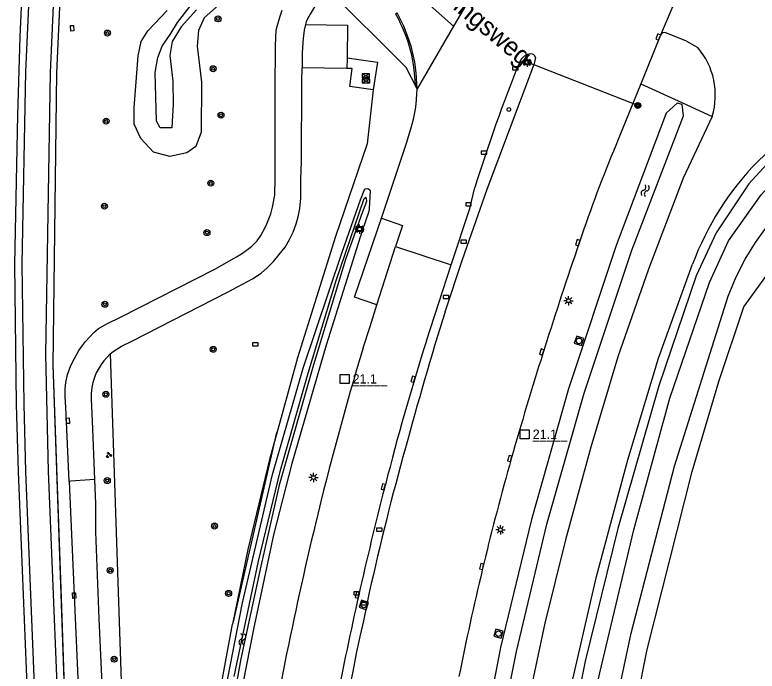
# Model space of a CAD drawing. Extents: x 124000 to 129000, y 395500 to 397503.
# Drawn here: x 124748.5 to 124848.4, y 396797.1 to 396885.3 of the extents above; entities that cross this region are included whole.
import ezdxf

# ---------------------------------------------------------------- set-up
doc = ezdxf.new("R2010")
doc.units = 0
for name, color, linetype in [('gg-afsc-draadraster', 7, 'Continuous'), ('gg-afsc-hekwerk', 7, 'Continuous'), ('gg-afsc-lijn draadraster', 7, 'Continuous'), ('gg-anno-openbare ruimte label', 7, 'Continuous'), ('gg-knt-bovenkant onderkant talud', 7, 'Continuous'), ('gg-knt-verharding', 7, 'Continuous'), ('gg-knt-verharding nz', 7, 'Continuous'), ('gg-kntw-bovenkant insteek waterloop', 7, 'Continuous'), ('gg-kntw-waterlijn', 7, 'Continuous'), ('gt-anno-nummer hm paal', 7, 'Continuous'), ('gt-grn-groengrens', 7, 'Continuous'), ('gt-grn-weggrens revisie', 7, 'Continuous'), ('gt-knt-lijn portaal', 7, 'Continuous'), ('gt-symb-boom', 7, 'Continuous'), ('gt-symb-bord', 7, 'Continuous'), ('gt-symb-groenvak', 7, 'Continuous'), ('gt-symb-hm paal', 7, 'Continuous'), ('gt-symb-kast', 7, 'Continuous'), ('gt-symb-kolk', 7, 'Continuous'), ('gt-symb-kolk center center', 7, 'Continuous'), ('gt-symb-lichtmast', 7, 'Continuous'), ('gt-symb-portaalmast', 7, 'Continuous'), ('gt-symb-rioolschacht', 7, 'Continuous'), ('gt-symb-verkeersregelinstallatiepaal', 7, 'Continuous'), ('gt-symb-watersymbool', 7, 'Continuous'), ('gx-grn-maaiveld', 7, 'Continuous')]:
    doc.layers.add(name, color=color, linetype=linetype)

# ---------------------------------------------------------------- blocks, each defined once
blk = doc.blocks.new('gt0-KOLK')
at = {"layer": 'gt-symb-kolk'}
blk.add_lwpolyline([(0, 0), (0.375, 0), (0.375, 0.4), (-0.375, 0.4), (-0.375, 0), (0, 0)], dxfattribs=at)
blk = doc.blocks.new('gt0-PORTM')
at = {"layer": 'gt-symb-portaalmast'}
for radius in [0.4, 0.33, 0.27, 0.21, 0.15]:
    blk.add_circle((0, 0), radius, dxfattribs=at)
blk = doc.blocks.new('gt0-WA')
at = {"layer": 'gt-symb-watersymbool'}
for centre, start, end in [((-0.323, 0.022), 28.07249, 151.92751), ((0.427, 0.422), 208.07248, 331.92751), ((-0.323, -0.428), 28.07249, 151.92751), ((0.427, -0.028), 208.07248, 331.92751)]:
    blk.add_arc(centre, 0.425, start, end, dxfattribs=at)
blk = doc.blocks.new('gt0-RS')
at = {"layer": 'gt-symb-rioolschacht'}
blk.add_lwpolyline([(-0.5, -0.5), (0.5, -0.5), (0.5, 0.5), (-0.5, 0.5)], close=True, dxfattribs=at)
blk.add_circle((0, 0), 0.375, dxfattribs=at)
blk = doc.blocks.new('gt0-LMAST')
at = {"layer": 'gt-symb-lichtmast'}
for p, q in [((-0.182, 0.173), (-0.447, 0.438)), ((-0.005, 0.246), (-0.005, 0.621)), ((0.172, 0.173), (0.437, 0.438)), ((-0.255, -0.004), (-0.63, -0.004)), ((-0.182, -0.181), (-0.447, -0.446)), ((-0.005, -0.254), (-0.005, -0.629)), ((0.437, -0.446), (0.172, -0.181)), ((0.245, -0.004), (0.62, -0.004))]:
    blk.add_line(p, q, dxfattribs=at)
blk.add_circle((-0.005, -0.004), 0.25, dxfattribs=at)
blk = doc.blocks.new('gt0-HMpaal')
at = {"layer": 'gt-symb-hm paal'}
blk.add_lwpolyline([(-0.6, 0.6), (0.6, 0.6), (0.6, -0.6), (-0.6, -0.6)], close=True, dxfattribs=at)
blk = doc.blocks.new('gt0-KAST')
at = {"layer": 'gt-symb-kast'}
for p, q in [((-0.501, -0.249), (0.501, 0.249)), ((-0.501, 0.249), (0.501, -0.249))]:
    blk.add_line(p, q, dxfattribs=at)
blk.add_lwpolyline([(0.501, 0.249), (-0.501, 0.249), (-0.501, -0.249), (0.501, -0.249)], close=True, dxfattribs=at)
blk = doc.blocks.new('gt0-BORD')
at = {"layer": 'gt-symb-bord'}
blk.add_lwpolyline([(-0.5, 0.295), (-0.5, -0.295), (0.5, -0.295), (0.5, 0.295), (-0.5, 0.295)], dxfattribs=at)
blk.add_lwpolyline([(-0.417, -0.212), (0.417, -0.212), (0.417, 0.212), (-0.417, 0.212)], close=True, dxfattribs=at)
blk = doc.blocks.new('gt0-BOOM')
at = {"layer": 'gt-symb-boom'}
for radius in [0.4, 0.2]:
    blk.add_circle((0, 0), radius, dxfattribs=at)
blk = doc.blocks.new('gt0-VIPAAL')
at = {"layer": 'gt-symb-verkeersregelinstallatiepaal'}
blk.add_circle((0, 0), 0.25, dxfattribs=at)
blk = doc.blocks.new('gt0-GRVAK')
at = {"layer": 'gt-symb-groenvak'}
for p, q in [((-0.11, 0.189), (-0.228, 0.24)), ((-0.182, 0.153), (0.088, 0.153)), ((-0.091, 0.211), (-0.156, 0.322)), ((-0.047, 0.214), (-0.047, 0.393)), ((-0.004, 0.211), (0.061, 0.322)), ((0.015, 0.189), (0.133, 0.24)), ((0.262, -0.052), (0.197, 0.059)), ((0.305, -0.049), (0.305, 0.13)), ((0.349, -0.052), (0.414, 0.059)), ((-0.245, -0.228), (-0.363, -0.177)), ((-0.318, -0.264), (-0.047, -0.264)), ((-0.226, -0.206), (-0.291, -0.095)), ((-0.183, -0.203), (-0.183, -0.024)), ((-0.139, -0.206), (-0.074, -0.095)), ((-0.12, -0.228), (-0.002, -0.177)), ((0.243, -0.074), (0.125, -0.023)), ((0.17, -0.11), (0.441, -0.11)), ((0.368, -0.074), (0.486, -0.023))]:
    blk.add_line(p, q, dxfattribs=at)
blk = doc.blocks.new('gt0-KOLKCC')
at = {"layer": 'gt-symb-kolk center center'}
blk.add_lwpolyline([(-0.375, 0.2), (0.375, 0.2), (0.375, -0.2), (-0.375, -0.2)], close=True, dxfattribs=at)

msp = doc.modelspace()

# ---------------------------------------------------------------- linework, layer by layer
at = {"layer": 'gg-afsc-draadraster'}
msp.add_lwpolyline([(124820.013, 396699.179), (124820.083, 396715.173), (124820.232, 396720.364), (124822.501, 396749.715), (124824.3, 396763.179), (124826.222, 396776.512), (124828.088, 396786.558), (124831.396, 396802.197), (124837.239, 396824.642), (124844.473, 396847.524), (124845.543, 396850.093), (124846.747, 396852.464), (124848.154, 396854.73), (124849.824, 396857.075), (124858.419, 396867.513)], dxfattribs=at)
at = {"layer": 'gg-afsc-hekwerk'}
msp.add_lwpolyline([(124759.38, 396710.74), (124755.634, 396783.08), (124753.682, 396838.231), (124754.182, 396877.515), (124755.955, 396916.668)], dxfattribs=at)
at = {"layer": 'gg-afsc-lijn draadraster'}
msp.add_line((124783.72, 396829.162), (124777.854, 396803.558), dxfattribs=at)
at = {"layer": 'gg-knt-bovenkant onderkant talud'}
msp.add_lwpolyline([(124822.564, 396699.278), (124822.903, 396713.454), (124824.661, 396738.834), (124825.256, 396746.56), (124827.056, 396763.66), (124828.802, 396774.037), (124830.867, 396786.503), (124833.575, 396800.029), (124839.594, 396823.963), (124843.199, 396836.04), (124846.57, 396846.056), (124850.8, 396851.948)], dxfattribs=at)
at = {"layer": 'gg-knt-verharding'}
for p, q in [((124835.38, 396882.586), (124832.712, 396876.032)), ((124838.863, 396881.775), (124836.078, 396882.903)), ((124838.863, 396881.775), (124840.359, 396880.945)), ((124832.712, 396876.032), (124829.68, 396868.564)), ((124848.355, 396865.523), (124851.006, 396868.084)), ((124824.787, 396855.717), (124824.412, 396854.624)), ((124797.226, 396846.331), (124799.744, 396854.174)), ((124803.877, 396841.511), (124807.226, 396851.707)), ((124815.533, 396826.526), (124815.282, 396825.625)), ((124798.357, 396822.149), (124798.267, 396821.835)), ((124808.457, 396797.379), (124808.246, 396796.387))]:
    msp.add_line(p, q, dxfattribs=at)
for points in [[(124818.529, 396879.592), (124818.477, 396879.183), (124818.304, 396878.592)], [(124806.392, 396845.399), (124808.754, 396852.437), (124812.029, 396861.904), (124818.051, 396877.832), (124818.304, 396878.592)], [(124842.318, 396871.666), (124838.42, 396863.381), (124833.725, 396851.122), (124829.62, 396839.34), (124825.983, 396827.223), (124822.6, 396814.773), (124819.808, 396803.556), (124816.441, 396787.758), (124813.837, 396771.712), (124811.667, 396754.763), (124810.203, 396737.809), (124809.074, 396719.01), (124808.896, 396703.076)], [(124797.859, 396857.999), (124801.219, 396868.062), (124801.795, 396869.985)], [(124807.226, 396851.707), (124809.71, 396859.304), (124810.382, 396862.089)], [(124797.226, 396846.331), (124794.201, 396847.356), (124797.859, 396857.999)], [(124797.859, 396857.999), (124800.673, 396857.026), (124799.744, 396854.174)], [(124814.177, 396707.412), (124814.434, 396721.809), (124815.265, 396735.042), (124816.512, 396750.349), (124818.326, 396765.688), (124820.487, 396780.485), (124823.023, 396793.705), (124826.755, 396809.814), (124830.977, 396825.495), (124835.088, 396839.152), (124839.682, 396851.814)], [(124795.369, 396840.546), (124796.309, 396843.432), (124797.226, 396846.331)], [(124796.194, 396807.661), (124795.405, 396803.892), (124794.953, 396801.953)]]:
    msp.add_lwpolyline(points, dxfattribs=at)
for centre, radius, start, end in [((124835.908, 396882.351), 0.578, 72.86521, 155.98559), ((124832.804, 396874.504), 9.928, 343.39083, 40.45183), ((124818.079, 396878.25), 1.824, 94.45874, 155.36281), ((124817.979, 396879.514), 0.556, 8.11559, 94.28208), ((125027.103, 396794.281), 227.081, 158.09166, 162.62601), ((124782.703, 396875.685), 19.925, 343.37635, 359.04471), ((125007.742, 396793.391), 193.28, 157.11177, 161.18785), ((124876.038, 396838.412), 38.747, 135.5973, 159.76371), ((125383.551, 396662.484), 591.231, 161.035419, 163.89139), ((125250.716, 396706.039), 465.666, 162.58619, 164.93069), ((125139.548, 396735.345), 352.06, 162.44891, 165.72597), ((125212.392, 396714.688), 435.601, 163.20616, 166.42726), ((125161.507, 396726.519), 374.216, 164.40752, 167.47701), ((125180.221, 396722.498), 379.23, 164.22044, 168.61186), ((125272.386, 396700.162), 489.482, 165.60678, 169.094), ((125267.899, 396701.714), 492.603, 166.47549, 170.91701), ((125510.359, 396655.849), 730.172, 168.457461, 170.029078)]:
    msp.add_arc(centre, radius, start, end, dxfattribs=at)
at = {"layer": 'gg-knt-verharding nz'}
msp.add_line((124839.921, 396893.347), (124835.38, 396882.586), dxfattribs=at)
at = {"layer": 'gg-kntw-bovenkant insteek waterloop'}
for points in [[(124806.413, 396692.247), (124806.146, 396711.167), (124806.637, 396728.332), (124807.854, 396746.225), (124810.08, 396765.886), (124812.639, 396783.003), (124816.014, 396799.727), (124820.095, 396816.858), (124825.097, 396834.491), (124831.511, 396853.689), (124838.433, 396871.724), (124838.256, 396873.281), (124837.594, 396873.455), (124836.139, 396872.088), (124829.383, 396854.324), (124822.973, 396835.044), (124817.992, 396817.504), (124813.85, 396800.299), (124810.555, 396783.323), (124808.002, 396765.983), (124805.831, 396746.365), (124804.631, 396728.673), (124804.085, 396711.233), (124804.281, 396692.296)], [(124852.568, 396868.625), (124851.592, 396867.354), (124847.232, 396862.618), (124842.846, 396856.025), (124840.145, 396850.258), (124835.154, 396835.474), (124829.61, 396816.277), (124825.222, 396798.437), (124821.651, 396780.387), (124819.119, 396763.426), (124817.031, 396745.202), (124815.931, 396727.225), (124815.605, 396713.346)], [(124815.605, 396713.346), (124817.753, 396713.346), (124818.009, 396726.766), (124819.222, 396745.231), (124821.034, 396762.339), (124823.493, 396780.248), (124827.178, 396796.897), (124831.761, 396816.101), (124836.629, 396833.777), (124841.935, 396849.343), (124844.503, 396854.958), (124848.914, 396861.116), (124853.86, 396866.625), (124854.424, 396867.427)]]:
    msp.add_lwpolyline(points, dxfattribs=at)
at = {"layer": 'gg-kntw-waterlijn'}
for points in [[(124781.288, 396811.879), (124784.265, 396824.122), (124787.995, 396837.155), (124791.755, 396849.627), (124795.527, 396860.625), (124795.685, 396860.789), (124795.738, 396860.795), (124795.793, 396860.653), (124795.831, 396860.28), (124795.7, 396859.85), (124795.291, 396858.84), (124793.013, 396852.423), (124788.709, 396838.296), (124784.075, 396822.118), (124781.622, 396811.205), (124778.933, 396798.776), (124777.491, 396790.749)], [(124778.016, 396796.375), (124781.288, 396811.879)]]:
    msp.add_lwpolyline(points, dxfattribs=at)
at = {"layer": 'gt-grn-groengrens'}
for p, q in [((124832.712, 396876.032), (124837.729, 396873.752)), ((124837.729, 396873.752), (124842.318, 396871.666))]:
    msp.add_line(p, q, dxfattribs=at)
msp.add_lwpolyline([(124766.657, 396718.624), (124768.688, 396721.592), (124769.253, 396729.69), (124768.876, 396733.645), (124769.065, 396740.99), (124769.253, 396745.698), (124772.831, 396776.397), (124777.816, 396803.404)], dxfattribs=at)
at = {"layer": 'gt-grn-weggrens revisie'}
msp.add_line((124799.744, 396854.174), (124807.226, 396851.707), dxfattribs=at)
at = {"layer": 'gt-knt-lijn portaal'}
msp.add_line((124832.302, 396873.124), (124817.417, 396878.938), dxfattribs=at)
at = {"layer": 'gx-grn-maaiveld'}
for p, q in [((124809.897, 396887.856), (124807.537, 396883.798)), ((124807.537, 396883.798), (124802.625, 396875.353)), ((124793.215, 396879.556), (124793.175, 396878.091)), ((124793.175, 396878.091), (124787.163, 396878.199))]:
    msp.add_line(p, q, dxfattribs=at)
for points in [[(124755.338, 396725.174), (124755.247, 396729.317), (124753.621, 396750), (124751.775, 396780.891), (124750.031, 396823.955), (124749.776, 396832.987), (124749.538, 396851.815), (124750.036, 396877.691), (124751.937, 396920.062), (124756.541, 396968.751), (124756.622, 396969.603), (124757.548, 396978.144), (124760.669, 397000), (124762.21, 397010.646), (124774.15, 397090.414)], [(124807.537, 396883.798), (124787.432, 396901.653), (124779.635, 396912.37), (124774.258, 396922.099), (124771.779, 396928.467), (124770.999, 396931.175), (124770.447, 396933.225), (124769.666, 396937.087), (124769.199, 396939.966), (124768.835, 396943.86), (124768.717, 396946.148), (124768.779, 396952.89), (124769.066, 396956.893), (124770.081, 396964.785), (124771.361, 396972.628), (124773.766, 396987.284), (124776.186, 397002.124)], [(124754.256, 396729.163), (124754.063, 396731.616), (124752.623, 396749.931), (124750.776, 396780.841), (124749.032, 396823.921), (124748.776, 396832.967), (124748.538, 396851.818), (124748.923, 396871.815), (124749.244, 396882.341), (124750.939, 396920.132), (124755.113, 396964.275), (124755.563, 396969.029)], [(124758.648, 396710.476), (124756.973, 396743.846), (124756.64, 396750), (124754.812, 396780.994), (124753.047, 396823.981), (124752.727, 396839.676), (124753.34, 396877.554), (124755.222, 396919.684)], [(124759.38, 396710.74), (124756.126, 396773.582), (124755.634, 396783.08), (124754.79, 396806.923), (124753.682, 396838.231), (124754.182, 396877.515), (124755.072, 396897.178), (124755.955, 396916.668), (124755.991, 396916.666)], [(124802.625, 396875.353), (124801.15, 396878.238), (124790.467, 396888.961)], [(124776.684, 396887.327), (124774.004, 396884.937), (124773.255, 396883.233), (124773.071, 396881.099), (124773.616, 396876.276), (124773.588, 396869.562), (124772.883, 396867.636), (124771.68, 396866.764), (124769.374, 396866.264), (124767.168, 396866.841), (124765.488, 396868.708), (124764.6, 396870.614), (124764.562, 396872.809), (124765.104, 396879.829), (124765.505, 396881.731), (124766.4, 396883.175), (124769.035, 396885.913)], [(124772.982, 396885.99), (124770.881, 396883.683), (124769.688, 396881.747), (124769.363, 396879.862), (124769.775, 396876.406), (124769.837, 396873.28), (124769.704, 396870.965), (124769.641, 396870.13), (124768.076, 396870.151), (124767.603, 396871.031), (124767.415, 396877.568), (124767.787, 396879.572), (124768.354, 396881.121), (124769.5, 396882.804), (124770.424, 396884.303), (124772.108, 396886.48)], [(124788.958, 396886.617), (124788.244, 396885.402), (124787.894, 396884.798), (124787.72, 396884.368), (124787.604, 396884.033)], [(124755.862, 396822.606), (124755.618, 396827.606), (124755.375, 396832.582), (124755.317, 396833.966), (124755.296, 396835.065), (124755.387, 396835.887), (124755.637, 396836.958), (124756.08, 396838.196), (124756.552, 396839.115), (124757.148, 396840.212), (124757.514, 396840.718), (124758.037, 396841.394), (124758.617, 396842.05), (124759.177, 396842.638), (124759.78, 396843.14), (124760.99, 396843.852), (124762.766, 396844.702), (124775.452, 396851.126), (124778.013, 396852.6), (124778.356, 396852.797), (124779.003, 396853.197), (124779.983, 396853.911), (124780.404, 396854.239), (124781.112, 396854.947), (124781.611, 396855.65), (124782.186, 396856.728), (124782.426, 396857.242), (124782.956, 396858.563), (124783.192, 396859.452), (124783.498, 396861.099), (124783.564, 396863.358), (124783.541, 396865.852), (124783.522, 396876.319), (124783.575, 396880.082), (124783.575, 396881.047), (124783.618, 396882.255), (124783.692, 396883.153), (124783.785, 396883.62), (124783.983, 396884.361), (124784.201, 396885.158), (124784.463, 396885.924)], [(124802.615, 396875.946), (124802.399, 396875.946), (124802.394, 396876.041), (124802.345, 396876.936), (124802.254, 396877.932), (124802.104, 396878.92), (124801.908, 396879.899), (124801.668, 396880.872), (124801.369, 396881.821), (124801.027, 396882.768), (124800.63, 396883.688), (124800.416, 396884.152), (124800.16, 396884.676), (124799.782, 396885.388), (124799.737, 396885.473), (124799.932, 396885.58)], [(124802.615, 396875.946), (124802.565, 396876.942), (124802.452, 396877.948), (124802.319, 396878.955), (124802.119, 396879.946), (124801.879, 396880.928), (124801.57, 396881.88), (124801.224, 396882.85), (124800.836, 396883.793), (124800.614, 396884.251), (124800.342, 396884.783), (124799.982, 396885.487), (124799.932, 396885.58)], [(124787.604, 396884.033), (124787.427, 396883.245), (124787.289, 396882.15), (124787.25, 396881.541), (124787.184, 396880.221), (124787.163, 396878.199)], [(124787.604, 396884.033), (124793.269, 396883.917), (124793.215, 396879.556)], [(124793.215, 396879.556), (124797.291, 396878.959), (124796.738, 396875.216)], [(124761.37, 396839.753), (124761.738, 396840.06), (124762.859, 396840.773), (124764.281, 396841.48), (124777.124, 396848.051), (124780.505, 396849.837), (124781.673, 396850.597), (124782.517, 396851.359), (124783.338, 396852.182), (124784.086, 396853.107), (124784.877, 396854.101), (124785.477, 396855.12), (124785.944, 396856.121), (124786.364, 396857.246), (124786.623, 396858.182), (124786.869, 396859.294), (124786.981, 396860.68), (124787.005, 396863.282), (124787.074, 396865.546), (124787.14, 396876.306), (124787.163, 396878.199)], [(124796.738, 396875.216), (124793.575, 396875.691), (124793.918, 396878.105), (124793.175, 396878.091)], [(124802.625, 396875.353), (124802.631, 396875.429), (124802.615, 396875.946)], [(124796.738, 396875.216), (124795.901, 396867.997), (124791.667, 396855.545), (124786.542, 396839.197), (124784.471, 396831.688), (124782.793, 396825.552), (124779.848, 396813.456), (124777.816, 396803.404)], [(124776.191, 396791.095), (124779.137, 396806.276), (124783.181, 396823.551), (124787.307, 396837.848), (124792.552, 396853.403), (124795.005, 396860.436), (124795.608, 396861.914), (124795.688, 396861.938), (124795.98, 396861.968), (124796.115, 396861.942), (124796.294, 396861.796), (124796.307, 396861.666), (124796.186, 396859.311), (124796.132, 396858.879), (124795.256, 396856.277), (124790.402, 396840.919), (124785.783, 396825.002), (124783.33, 396815.41)], [(124761.37, 396839.753), (124760.485, 396838.825), (124760.164, 396838.34), (124759.471, 396837.18), (124759.246, 396836.561), (124759.02, 396835.886), (124758.886, 396835.238), (124758.812, 396834.439), (124758.807, 396833.656), (124758.922, 396830.772), (124759.259, 396822.882)], [(124761.37, 396839.753), (124762.891, 396794.398), (124766.657, 396718.624)], [(124759.259, 396822.882), (124756.085, 396822.63), (124755.862, 396822.606)], [(124755.862, 396822.606), (124760.781, 396710.657), (124762.564, 396676.321)], [(124759.259, 396822.882), (124759.373, 396819.575), (124759.394, 396815.811), (124759.832, 396804.2), (124760.752, 396783.641), (124764.329, 396715.222)], [(124783.33, 396815.41), (124780.618, 396802.76), (124778.759, 396793.163)]]:
    msp.add_lwpolyline(points, dxfattribs=at)

# ---------------------------------------------------------------- block references
at = {"layer": 'gt-symb-boom'}
for p in [(124775.861, 396884.771), (124760.995, 396882.869), (124775.199, 396878.075), (124760.814, 396871.032), (124776.262, 396871.825), (124774.886, 396862.698), (124760.582, 396859.601), (124774.373, 396856.049), (124760.646, 396846.418), (124775.215, 396840.361), (124760.782, 396834.316), (124760.965, 396822.717), (124775.386, 396816.607), (124761.367, 396810.644), (124777.285, 396807.561), (124761.883, 396798.707)]:
    msp.add_blockref('gt0-BOOM', p, dxfattribs=at)
at = {"layer": 'gt-symb-bord'}
for p in [(124817.417, 396878.938), (124794.906, 396856.522)]:
    msp.add_blockref('gt0-BORD', p, dxfattribs=at)
at = {"layer": 'gt-symb-groenvak'}
msp.add_blockref('gt0-GRVAK', (124761.16, 396826.153), dxfattribs=at)
at = {"layer": 'gt-symb-hm paal'}
for p in [(124792.881, 396836.372), (124817.104, 396828.931)]:
    msp.add_blockref('gt0-HMpaal', p, dxfattribs=at)
at = {"layer": 'gt-symb-kast'}
for p in [(124795.724, 396877.133), (124795.759, 396876.425)]:
    msp.add_blockref('gt0-KAST', p, dxfattribs=at)
at = {"layer": 'gt-symb-kolk'}
for p, rotation in [((124835.242, 396882.262), 66.92177859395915), ((124824.412, 396854.624), 71.03974891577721), ((124819.58, 396839.941), 72.54344186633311), ((124802.268, 396836.287), 73.32270606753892), ((124815.282, 396825.625), 74.44827510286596), ((124798.267, 396821.835), 74.10181291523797), ((124811.49, 396811.116), 76.46414363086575), ((124794.771, 396807.293), 77.35314650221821)]:
    msp.add_blockref('gt0-KOLK', p, dxfattribs=dict(at, rotation=rotation))
for p in [(124815.834, 396877.934), (124811.64, 396866.603), (124809.538, 396859.63), (124808.898, 396854.641), (124806.524, 396847.209), (124780.875, 396840.834), (124797.542, 396815.93), (124794.499, 396807.348), (124795.481, 396806.014)]:
    msp.add_blockref('gt0-KOLK', p, dxfattribs=at)
at = {"layer": 'gt-symb-kolk center center'}
for p, rotation in [((124756.247, 396883.521), 92.29290049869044), ((124755.679, 396830.761), 92.80805306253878), ((124756.508, 396807.27), 92.80805306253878)]:
    msp.add_blockref('gt0-KOLKCC', p, dxfattribs=dict(at, rotation=rotation))
at = {"layer": 'gt-symb-lichtmast'}
for p in [(124817.417, 396878.938), (124794.906, 396856.522), (124823.008, 396846.9), (124788.698, 396823.13), (124813.829, 396816.115)]:
    msp.add_blockref('gt0-LMAST', p, dxfattribs=at)
at = {"layer": 'gt-symb-portaalmast'}
msp.add_blockref('gt0-PORTM', (124832.302, 396873.124), dxfattribs=at)
at = {"layer": 'gt-symb-rioolschacht'}
for p, rotation in [((124824.406, 396841.496), 71.0939390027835), ((124795.471, 396806.003), 70.96692019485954), ((124813.57, 396802.146), 74.44827510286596)]:
    msp.add_blockref('gt0-RS', p, dxfattribs=dict(at, rotation=rotation))
at = {"layer": 'gt-symb-verkeersregelinstallatiepaal'}
msp.add_blockref('gt0-VIPAAL', (124814.977, 396872.592), dxfattribs=at)
at = {"layer": 'gt-symb-watersymbool'}
for p, rotation in [((124833.309, 396861.753), -105.18978717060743), ((124779.141, 396801.429), -92.17836882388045)]:
    msp.add_blockref('gt0-WA', p, dxfattribs=dict(at, rotation=rotation))

# ---------------------------------------------------------------- texts
at = {"layer": 'gg-anno-openbare ruimte label'}
msp.add_text('Burgemeester Ballingsweg', height=2.5, rotation=320, dxfattribs=at).set_placement((124786.27, 396903.854))
at = {"layer": 'gt-anno-nummer hm paal'}
for p in [(124793.962, 396835.768), (124818.185, 396828.327)]:
    msp.add_text('21.1', height=1.25, dxfattribs=at).set_placement(p)
at = {"layer": 'gt-symb-hm paal'}
for p in [(124793.962, 396835.768), (124818.185, 396828.327)]:
    msp.add_text('_____', height=1.25, dxfattribs=at).set_placement(p)

doc.saveas('drawing.dxf')
